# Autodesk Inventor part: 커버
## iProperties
Created: 2012-05
Part Number: 커버
Document SubType Name: 모델링
Designer: SeoGD™
변환 표준: STEP AP214IS
파일 이름: C:\Users\SeoGD\Desktop\?쒗뿕\而ㅻ쾭-1.stp
전처리기: Build: 253, Release: 2010 SP1 - Date: Wed 07/29/2009
전송 단위: 밀리미터
불확실성: 0.01
Author: SeoGD™
